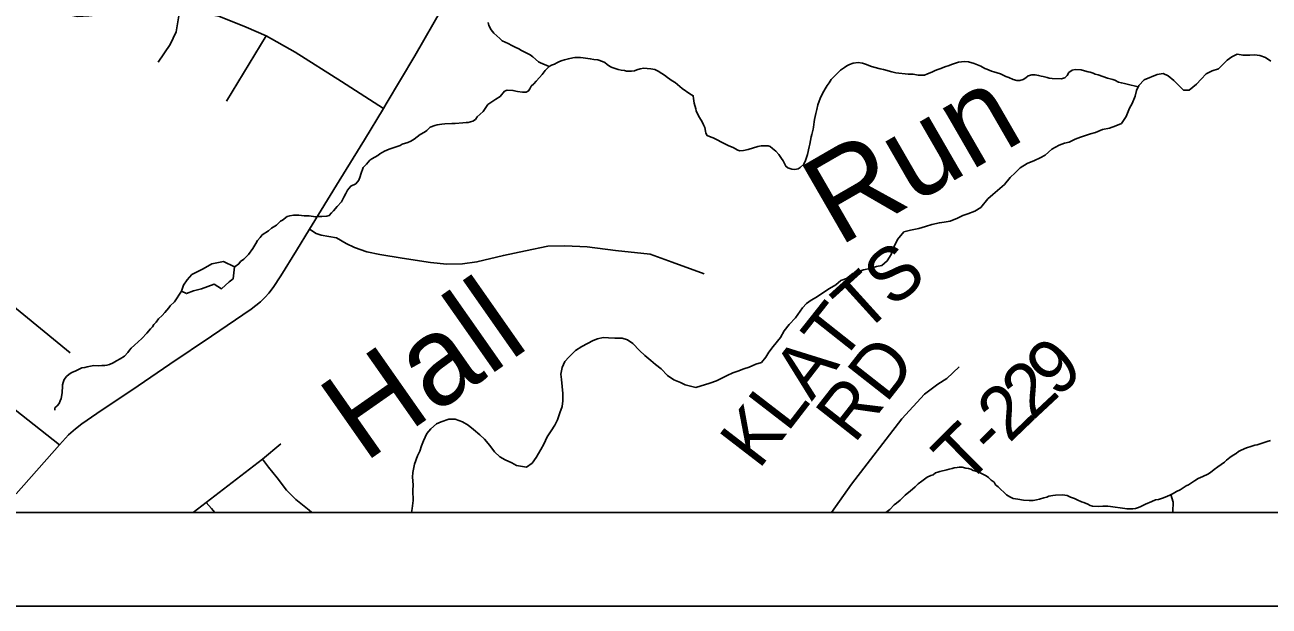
# Model space of a CAD drawing. Extents: x 44.2 to 78.2, y 4.5 to 26.5.
# Drawn here: x 49.072 to 50.4, y 18.501 to 19.122 of the extents above; entities that cross this region are included whole.
import ezdxf

# ---------------------------------------------------------------- set-up
doc = ezdxf.new("R2010")
doc.units = 0
for name, color, linetype in [('GM_X_County_Road', 7, 'Continuous'), ('GM_X_Minor_Lake', 7, 'Continuous'), ('GM_X_Minor_River', 7, 'Continuous'), ('GM_X_Minor_River_Text', 7, 'Continuous'), ('GM_X_Rail_Line', 7, 'Continuous'), ('GM_X_Township_Road', 7, 'Continuous'), ('GM_X_Township_Road_Text', 7, 'Continuous'), ('SH_Cut_Line', 7, 'Continuous'), ('SH_Data', 7, 'Continuous')]:
    doc.layers.add(name, color=color, linetype=linetype)

msp = doc.modelspace()

# ---------------------------------------------------------------- linework, layer by layer
at = {"layer": 'GM_X_County_Road'}
msp.add_lwpolyline([(49.0628, 18.6214), (49.1089, 18.6736), (49.1188, 18.6841), (49.126, 18.6906), (49.1329, 18.696), (49.149, 18.7071), (49.1929, 18.7364), (49.2268, 18.7596), (49.2711, 18.7894), (49.3137, 18.8184), (49.3237, 18.8263), (49.3285, 18.8311), (49.3323, 18.8354), (49.3372, 18.8416), (49.3453, 18.854), (49.3618, 18.881), (49.3758, 18.9036), (49.4074, 18.9552), (49.4346, 18.9991), (49.4549, 19.0327), (49.4578, 19.0375), (49.4882, 19.0889), (49.5183, 19.1414)], dxfattribs=at)
at = {"layer": 'GM_X_Minor_Lake'}
msp.add_lwpolyline([(49.2957, 18.8634), (49.2841, 18.8693), (49.2715, 18.8669), (49.2622, 18.8614), (49.2503, 18.8555), (49.2453, 18.8496), (49.2414, 18.844), (49.2393, 18.8375), (49.2446, 18.8351), (49.2519, 18.838), (49.2607, 18.8401), (49.2675, 18.8427), (49.2741, 18.8452), (49.2819, 18.8401), (49.2901, 18.8475), (49.2943, 18.8508), (49.2957, 18.8634)], dxfattribs=at)
at = {"layer": 'GM_X_Minor_River'}
for points in [[(49.6315, 19.0774), (49.6225, 19.0814), (49.6202, 19.0823), (49.6143, 19.0877), (49.6113, 19.0897), (49.6083, 19.0913), (49.6019, 19.0945), (49.5993, 19.0961), (49.5952, 19.0981), (49.5918, 19.0997), (49.5877, 19.1021), (49.5813, 19.1049), (49.5791, 19.1072), (49.5724, 19.1131), (49.5698, 19.1166), (49.5673, 19.1212), (49.5666, 19.1243)], [(49.8938, 18.9673), (49.8904, 18.9678), (49.8863, 18.9694), (49.8841, 18.971), (49.883, 18.9733), (49.8812, 18.9768), (49.8797, 18.9791), (49.8768, 18.9833), (49.8735, 18.9872), (49.8701, 18.99), (49.8675, 18.9919), (49.8652, 18.9927), (49.858, 18.9926), (49.8542, 18.9919), (49.8439, 18.9888), (49.8389, 18.9877), (49.8347, 18.9875), (49.8321, 18.9883), (49.828, 18.9911), (49.8235, 18.9927), (49.8163, 18.9963), (49.8103, 18.9995), (49.8066, 19.0011), (49.8043, 19.0019), (49.8002, 19.0036), (49.7987, 19.0062), (49.7984, 19.0085), (49.7977, 19.0123), (49.7963, 19.015), (49.7952, 19.0177), (49.7938, 19.02), (49.7912, 19.0239), (49.7883, 19.03), (49.788, 19.0323), (49.7863, 19.0384), (49.7856, 19.0434), (49.7853, 19.0461), (49.7816, 19.0484), (49.7734, 19.054), (49.7659, 19.0602), (49.7629, 19.0622), (49.7577, 19.0658), (49.7547, 19.0681), (49.7517, 19.0701), (49.748, 19.0725), (49.7442, 19.0741), (49.7401, 19.0749), (49.7363, 19.0754), (49.7325, 19.0755), (49.7287, 19.0749), (49.7252, 19.0738), (49.7226, 19.0727), (49.7195, 19.0724), (49.7169, 19.0725), (49.7142, 19.0726), (49.7119, 19.073), (49.7085, 19.0735), (49.7051, 19.0743), (49.6999, 19.076), (49.6972, 19.0772), (49.6935, 19.0796), (49.6909, 19.0815), (49.6886, 19.0827), (49.6834, 19.0844), (49.6792, 19.0849), (49.6754, 19.0857), (49.6678, 19.0867), (49.6652, 19.0871), (49.6591, 19.0869), (49.6568, 19.0866), (49.6522, 19.0856), (49.648, 19.0846), (49.6454, 19.0839), (49.6427, 19.0828), (49.6396, 19.0814), (49.6373, 19.0799), (49.6342, 19.0789), (49.6315, 19.0774), (49.6272, 19.0733), (49.6241, 19.0689), (49.6213, 19.0655), (49.6178, 19.0618), (49.6151, 19.0589), (49.6124, 19.0563), (49.6108, 19.0537), (49.6096, 19.0514), (49.6069, 19.05), (49.6031, 19.0501), (49.5978, 19.0506), (49.5929, 19.0519), (49.5868, 19.052), (49.5841, 19.0509), (49.5794, 19.0454), (49.5748, 19.0425), (49.5663, 19.037), (49.5612, 19.0295), (49.5549, 19.0236), (49.553, 19.021), (49.5503, 19.0192), (49.5453, 19.0178), (49.543, 19.0175)], [(49.8581, 18.7615), (49.8628, 18.7672), (49.8659, 18.7724), (49.8705, 18.7784), (49.8783, 18.7882), (49.8822, 18.7953), (49.8877, 18.8021), (49.8946, 18.8092), (49.902, 18.8197), (49.9063, 18.8245), (49.9113, 18.8279), (49.917, 18.8312), (49.9258, 18.8371), (49.9308, 18.8405), (49.9374, 18.8445), (49.9427, 18.849), (49.9488, 18.8512), (49.9558, 18.8564), (49.9619, 18.8585), (49.9672, 18.8604), (49.9737, 18.8618), (49.9809, 18.8639), (49.9866, 18.865), (49.9924, 18.8698), (49.9967, 18.8769), (49.9995, 18.8845), (50.0035, 18.8928), (50.0101, 18.901), (50.0173, 18.9028), (50.026, 18.9046), (50.0333, 18.9067), (50.0398, 18.9089), (50.0481, 18.9106), (50.0531, 18.9113), (50.0596, 18.9123), (50.0672, 18.9156), (50.0729, 18.9182), (50.0783, 18.92), (50.0859, 18.9229), (50.0921, 18.927), (50.0998, 18.936), (50.1052, 18.9408), (50.1102, 18.9449), (50.1175, 18.9516), (50.1234, 18.9591), (50.1288, 18.964), (50.1342, 18.9692), (50.1418, 18.974), (50.1495, 18.9769), (50.1556, 18.9799), (50.161, 18.9828), (50.1679, 18.9891), (50.1759, 18.9936), (50.1817, 18.9957), (50.1866, 18.9968), (50.1931, 18.9997), (50.1985, 19.0019), (50.2092, 19.0055), (50.2145, 19.007), (50.2221, 19.0103), (50.2294, 19.0116), (50.2362, 19.0142), (50.2423, 19.0167), (50.2474, 19.0239), (50.251, 19.0329), (50.2537, 19.0378), (50.2569, 19.0458), (50.2585, 19.0518), (50.2609, 19.0571), (50.2667, 19.0631), (50.2805, 19.0689), (50.2869, 19.0699), (50.2922, 19.0676), (50.2982, 19.0625), (50.3034, 19.0571), (50.3086, 19.0521), (50.3147, 19.052), (50.3224, 19.0587), (50.3274, 19.0639), (50.3328, 19.0695), (50.3393, 19.0728), (50.3458, 19.075), (50.3551, 19.084), (50.3601, 19.0877), (50.3658, 19.0906), (50.3722, 19.0894), (50.3794, 19.0896), (50.3844, 19.0899), (50.39, 19.0891), (50.3961, 19.0871), (50.4017, 19.0832)], [(50.2603, 19.0558), (50.2483, 19.0586), (50.2456, 19.0591), (50.2422, 19.0599), (50.2392, 19.0607), (50.2354, 19.0627), (50.2332, 19.0636), (50.2275, 19.0648), (50.2174, 19.0685), (50.2143, 19.0694), (50.2121, 19.0702), (50.2091, 19.0714), (50.2068, 19.0718), (50.203, 19.0727), (50.1993, 19.0739), (50.1928, 19.0741), (50.1898, 19.0734), (50.1863, 19.0709), (50.1843, 19.0679), (50.182, 19.0653), (50.1781, 19.0642), (50.1683, 19.0645), (50.1652, 19.065), (50.163, 19.0658), (50.1588, 19.0666), (50.1565, 19.0671), (50.1539, 19.0679), (50.1501, 19.0684), (50.1467, 19.0685), (50.1429, 19.0674), (50.1402, 19.0652), (50.1375, 19.0634), (50.134, 19.0624), (50.1306, 19.0624), (50.1268, 19.0637), (50.122, 19.0657), (50.1189, 19.0669), (50.1133, 19.0697), (50.1062, 19.0718), (50.1035, 19.0726), (50.0986, 19.0747), (50.0964, 19.0751), (50.0923, 19.0779), (50.0851, 19.0807), (50.0791, 19.0824), (50.0749, 19.0829), (50.0684, 19.0819), (50.0611, 19.0794), (50.0585, 19.0784), (50.0539, 19.077), (50.0496, 19.0752), (50.0462, 19.0741), (50.0435, 19.0731), (50.0408, 19.0716), (50.0381, 19.0706), (50.0354, 19.0695), (50.032, 19.0681), (50.0252, 19.0682), (50.0199, 19.0691), (50.0146, 19.0693), (50.0017, 19.0708), (49.9971, 19.0716), (49.9885, 19.0741), (49.9847, 19.075), (49.9779, 19.0767), (49.9745, 19.0779), (49.9719, 19.0787), (49.9692, 19.0799), (49.9658, 19.0808), (49.9613, 19.0817), (49.956, 19.0811), (49.9521, 19.0796), (49.9494, 19.0782), (49.9467, 19.0764), (49.9425, 19.0734), (49.9374, 19.0686), (49.9327, 19.0634), (49.9304, 19.0601), (49.9284, 19.0571), (49.926, 19.0534), (49.9232, 19.0485), (49.9208, 19.0433), (49.9196, 19.0403), (49.9184, 19.0365), (49.9171, 19.0316), (49.9162, 19.0271), (49.9149, 19.0207), (49.9145, 19.0184), (49.9136, 19.0127), (49.9132, 19.0105), (49.9119, 19.0048), (49.9111, 19.0022), (49.9097, 18.9946), (49.9089, 18.9916), (49.9072, 18.9833), (49.9063, 18.9803), (49.9051, 18.9769), (49.9035, 18.9732), (49.8996, 18.9695), (49.8973, 18.968), (49.8938, 18.9673)], [(49.543, 19.0175), (49.5396, 19.0172), (49.5312, 19.0167), (49.5278, 19.0164), (49.5202, 19.0162), (49.5171, 19.0159), (49.5122, 19.0153), (49.5095, 19.0146), (49.5045, 19.0128), (49.501, 19.0091), (49.4987, 19.0073), (49.4941, 19.0047), (49.4906, 19.0022), (49.4875, 19), (49.484, 18.9978), (49.4806, 18.9964), (49.4748, 18.9946), (49.4725, 18.9932), (49.4641, 18.9903), (49.461, 18.9893), (49.456, 18.9871), (49.451, 18.9842), (49.4487, 18.9824), (49.4425, 18.9788), (49.4402, 18.9773), (49.4367, 18.9732), (49.4332, 18.9695), (49.4307, 18.9624), (49.4299, 18.9601), (49.4283, 18.956), (49.4251, 18.9523), (49.4198, 18.9498), (49.4162, 18.9453), (49.4146, 18.9419), (49.4126, 18.9378), (49.4098, 18.933), (49.4055, 18.9281), (49.4016, 18.9233), (49.3993, 18.9211), (49.3969, 18.9185), (49.3943, 18.9178), (49.3889, 18.9172), (49.3859, 18.9173), (49.3821, 18.917), (49.3756, 18.9179), (49.3703, 18.9181), (49.3646, 18.9186), (49.3589, 18.9187), (49.3548, 18.9181), (49.3521, 18.9174), (49.347, 18.9133), (49.3447, 18.9123), (49.3405, 18.9082), (49.3354, 18.9049), (49.3319, 18.902), (49.3254, 18.8976), (49.323, 18.895), (49.3203, 18.8917), (49.3187, 18.8883), (49.3155, 18.8831), (49.3108, 18.8767), (49.3057, 18.8719), (49.3022, 18.8694), (49.3003, 18.8668), (49.2964, 18.8638), (49.2957, 18.8634)], [(49.2393, 18.8375), (49.2316, 18.8261), (49.227, 18.822), (49.2258, 18.8198), (49.2215, 18.815), (49.2187, 18.8116), (49.2148, 18.8079), (49.2121, 18.8046), (49.2098, 18.802), (49.2082, 18.7997), (49.2062, 18.7975), (49.2023, 18.7927), (49.1968, 18.7871), (49.1929, 18.7834), (49.1891, 18.7801), (49.1856, 18.7768), (49.1836, 18.7746), (49.182, 18.772), (49.1785, 18.7683)], [(49.4846, 18.6014), (49.4855, 18.6057), (49.4864, 18.614), (49.4862, 18.625), (49.4864, 18.6307), (49.4857, 18.6391), (49.4862, 18.644), (49.4879, 18.6528), (49.4911, 18.6618), (49.4935, 18.6667), (49.4955, 18.6724), (49.4974, 18.6777), (49.501, 18.6856), (49.5053, 18.6908), (49.5114, 18.696), (49.5164, 18.6982), (49.5244, 18.7008), (49.5312, 18.701), (49.5392, 18.6982), (49.5452, 18.6947), (49.5508, 18.6901), (49.5575, 18.6842), (49.5627, 18.6796), (49.5683, 18.673), (49.5731, 18.6661), (49.5791, 18.6607), (49.5847, 18.6576), (49.5918, 18.6544), (49.5967, 18.6516), (49.6073, 18.6499), (49.6134, 18.654), (49.6177, 18.66), (49.6228, 18.6687), (49.6259, 18.6743), (49.6295, 18.6822), (49.6338, 18.6886), (49.6377, 18.6946), (49.6404, 18.7003), (49.6429, 18.7078), (49.6453, 18.7146), (49.6461, 18.7207), (49.6463, 18.7283), (49.6453, 18.7359), (49.6446, 18.7432), (49.644, 18.7489), (49.6456, 18.7561), (49.6484, 18.7625), (49.6527, 18.7673), (49.6596, 18.7741), (49.6665, 18.7785), (49.6726, 18.7818), (49.6784, 18.7851), (49.6833, 18.7866), (49.6891, 18.788), (49.6948, 18.7879), (49.7016, 18.7874), (49.7095, 18.7873), (49.7152, 18.7856), (49.7208, 18.7817), (49.7279, 18.7744), (49.7338, 18.769), (49.7402, 18.7636), (49.745, 18.7593), (49.751, 18.7546), (49.7577, 18.7477), (49.7645, 18.743), (49.7716, 18.7402), (49.7769, 18.7375), (49.7882, 18.7346), (49.8031, 18.7393), (49.8103, 18.7418), (49.8214, 18.7477), (49.8276, 18.7503), (49.8329, 18.7521), (49.8394, 18.7546), (49.8451, 18.7564), (49.852, 18.7597), (49.8581, 18.7615)], [(49.1785, 18.7683), (49.1739, 18.7654), (49.17, 18.7632), (49.1662, 18.761), (49.1623, 18.7592), (49.1596, 18.7585), (49.1574, 18.7582), (49.1543, 18.7583), (49.1505, 18.758), (49.1456, 18.7581), (49.1387, 18.7568), (49.136, 18.7561), (49.133, 18.7558), (49.1265, 18.7526), (49.1222, 18.7508), (49.1195, 18.7489), (49.1164, 18.7464), (49.1141, 18.7434), (49.1128, 18.74), (49.1124, 18.7377), (49.1123, 18.7343), (49.1119, 18.7313), (49.1118, 18.729), (49.1109, 18.723), (49.1097, 18.7207), (49.1085, 18.7177), (49.1065, 18.7151), (49.1042, 18.7129), (49.1041, 18.7106)], [(50.4015, 18.6782), (50.3977, 18.6772), (50.387, 18.6737), (50.3847, 18.6733), (50.3805, 18.6719), (50.3759, 18.6702), (50.3701, 18.668), (50.3674, 18.6666), (50.3647, 18.6644), (50.3616, 18.6626), (50.3581, 18.66), (50.3546, 18.6571), (50.3523, 18.6552), (50.3488, 18.6527), (50.345, 18.6501), (50.3411, 18.6472), (50.3372, 18.6439), (50.3345, 18.6424), (50.3291, 18.6399), (50.3241, 18.6377), (50.3203, 18.6352), (50.3137, 18.6308), (50.3114, 18.6297), (50.3072, 18.6268), (50.3048, 18.6257), (50.301, 18.6236), (50.2975, 18.6217), (50.2948, 18.6203), (50.2906, 18.6185), (50.286, 18.6167), (50.2818, 18.6153), (50.2787, 18.6147), (50.2749, 18.6132), (50.268, 18.6104), (50.2657, 18.6093), (50.2622, 18.6075), (50.2595, 18.6064), (50.2572, 18.6057), (50.2542, 18.6051), (50.2481, 18.6052), (50.2458, 18.6056), (50.2307, 18.6076), (50.2277, 18.608), (50.2224, 18.6082), (50.2174, 18.6079), (50.2113, 18.6081), (50.2091, 18.6089), (50.2065, 18.6101), (50.202, 18.6121), (50.1997, 18.6129), (50.1952, 18.6149), (50.1922, 18.6162), (50.188, 18.6178), (50.1843, 18.6194), (50.182, 18.6198), (50.1794, 18.6203), (50.1718, 18.6197), (50.1691, 18.6194), (50.1649, 18.6188), (50.1626, 18.6177), (50.1595, 18.617), (50.1549, 18.6156), (50.1515, 18.6149), (50.1481, 18.6143), (50.1439, 18.614), (50.1378, 18.6145)], [(50.1378, 18.6145), (50.1318, 18.6155), (50.1269, 18.6163), (50.1231, 18.618), (50.1197, 18.6203), (50.1108, 18.6289), (50.1079, 18.6309), (50.1064, 18.6336), (50.1034, 18.6359), (50.1005, 18.6387), (50.0978, 18.6406), (50.0952, 18.6418), (50.0907, 18.6439), (50.087, 18.6455), (50.0839, 18.6463), (50.0817, 18.6475), (50.0791, 18.6483), (50.0764, 18.6488), (50.0722, 18.6496), (50.0692, 18.6497), (50.0669, 18.6494), (50.0639, 18.6491), (50.0616, 18.6484), (50.0585, 18.6477), (50.0558, 18.647), (50.0486, 18.645), (50.0463, 18.6443), (50.044, 18.6436), (50.0413, 18.6417), (50.039, 18.641), (50.0351, 18.6389), (50.0293, 18.6348), (50.0255, 18.6319), (50.022, 18.6286), (50.0169, 18.6242), (50.0138, 18.6216), (50.0115, 18.6197), (50.006, 18.6146), (50.0021, 18.6113), (49.9998, 18.6094), (49.9951, 18.6046), (49.991, 18.6014)], [(50.2951, 18.6204), (50.2974, 18.6124), (50.2972, 18.6025), (50.297, 18.6014)]]:
    msp.add_lwpolyline(points, dxfattribs=at)
at = {"layer": 'GM_X_Rail_Line'}
msp.add_lwpolyline([(48.642, 18.6014), (53.1359, 18.6014)], dxfattribs=at)
at = {"layer": 'GM_X_Township_Road'}
for p, q in [((49.3297, 19.1102), (49.2872, 19.0405)), ((50.0559, 18.7443), (50.0691, 18.7568))]:
    msp.add_line(p, q, dxfattribs=at)
for points in [[(49.4549, 19.0327), (49.4099, 19.0615), (49.3606, 19.0927), (49.3297, 19.1102), (49.3082, 19.1195), (49.2792, 19.1312), (49.2375, 19.1379), (49.2212, 19.1397), (49.1938, 19.1389), (49.1575, 19.1334), (49.1403, 19.1314), (49.1283, 19.1307), (49.1161, 19.1332), (49.0765, 19.1551), (49.038, 19.1805), (49.0107, 19.1981)], [(49.2142, 19.082), (49.227, 19.101), (49.2335, 19.1145), (49.2375, 19.1379), (49.2411, 19.167)], [(49.3758, 18.9036), (49.3831, 18.8992), (49.3882, 18.8975), (49.4047, 18.8946), (49.4148, 18.8883), (49.4238, 18.8843), (49.437, 18.8795), (49.4509, 18.8766), (49.4747, 18.8727), (49.5049, 18.8683), (49.5223, 18.8664), (49.539, 18.8668), (49.5545, 18.8688), (49.5827, 18.8758), (49.6063, 18.8805), (49.6301, 18.8855), (49.6483, 18.8861), (49.6722, 18.8849), (49.7023, 18.8811), (49.7392, 18.8772), (49.7629, 18.8684), (49.797, 18.856)], [(48.9202, 18.7941), (48.9512, 18.8144), (48.985, 18.8392), (49.0065, 18.8539), (49.011, 18.8538), (49.0167, 18.8518), (49.0388, 18.8383), (49.1204, 18.7719)], [(49.1089, 18.6736), (49.0091, 18.7521), (48.9753, 18.7804), (48.96, 18.8059), (48.9512, 18.8144)], [(49.933, 18.6014), (49.9542, 18.6315), (50.008, 18.7015), (50.032, 18.7275), (50.0465, 18.7383), (50.0559, 18.7443)], [(49.2516, 18.6014), (49.2657, 18.6119), (49.3256, 18.6582), (49.3453, 18.6747)], [(49.3256, 18.6582), (49.3319, 18.6496), (49.3413, 18.6382), (49.3513, 18.6252), (49.3611, 18.6153), (49.3754, 18.6038), (49.3783, 18.6014)], [(49.2657, 18.6119), (49.2714, 18.6057), (49.2747, 18.6014)]]:
    msp.add_lwpolyline(points, dxfattribs=at)
at = {"layer": 'SH_Cut_Line'}
msp.add_lwpolyline([(48.642, 18.6014), (53.1359, 18.6014), (53.1359, 25.4014)], dxfattribs=at)
at = {"layer": 'SH_Data'}
for p, q in [((46.3359, 18.6014), (53.1359, 18.6014)), ((46.2359, 18.5014), (53.2359, 18.5014))]:
    msp.add_line(p, q, dxfattribs=at)

# ---------------------------------------------------------------- texts
at = {"layer": 'GM_X_Minor_River_Text'}
for s, rotation, p in [('Run', 30.0038, (49.9405, 18.8845)), ('Hall', 35.0042, (49.434, 18.6536))]:
    msp.add_text(s, height=0.0947, rotation=rotation, dxfattribs=at).set_placement(p)
at = {"layer": 'GM_X_Township_Road_Text'}
for s, height, rotation, p in [('S', 0.0568, 39.5926, (49.9978, 18.8186)), ('T', 0.0568, 42.1959, (49.9668, 18.7905)), ('T', 0.0568, 51.63, (49.9422, 18.7589)), ('A', 0.0568, 52.3848, (49.9118, 18.7195)), ('RD', 0.05682, 51.8658, (49.9572, 18.6737)), ('9', 0.0568, 41.9075, (50.1729, 18.7225)), ('2', 0.0568, 43.0494, (50.1475, 18.6988)), ('2', 0.0568, 43.9034, (50.1225, 18.6747)), ('L', 0.0568, 52.3904, (49.8858, 18.6858)), ('K', 0.0568, 52.3899, (49.8553, 18.6462)), ('T', 0.0568, 44.6697, (50.0757, 18.6286)), ('-', 0.0568, 44.4701, (50.1059, 18.6584))]:
    msp.add_text(s, height=height, rotation=rotation, dxfattribs=at).set_placement(p)

doc.saveas('drawing.dxf')
